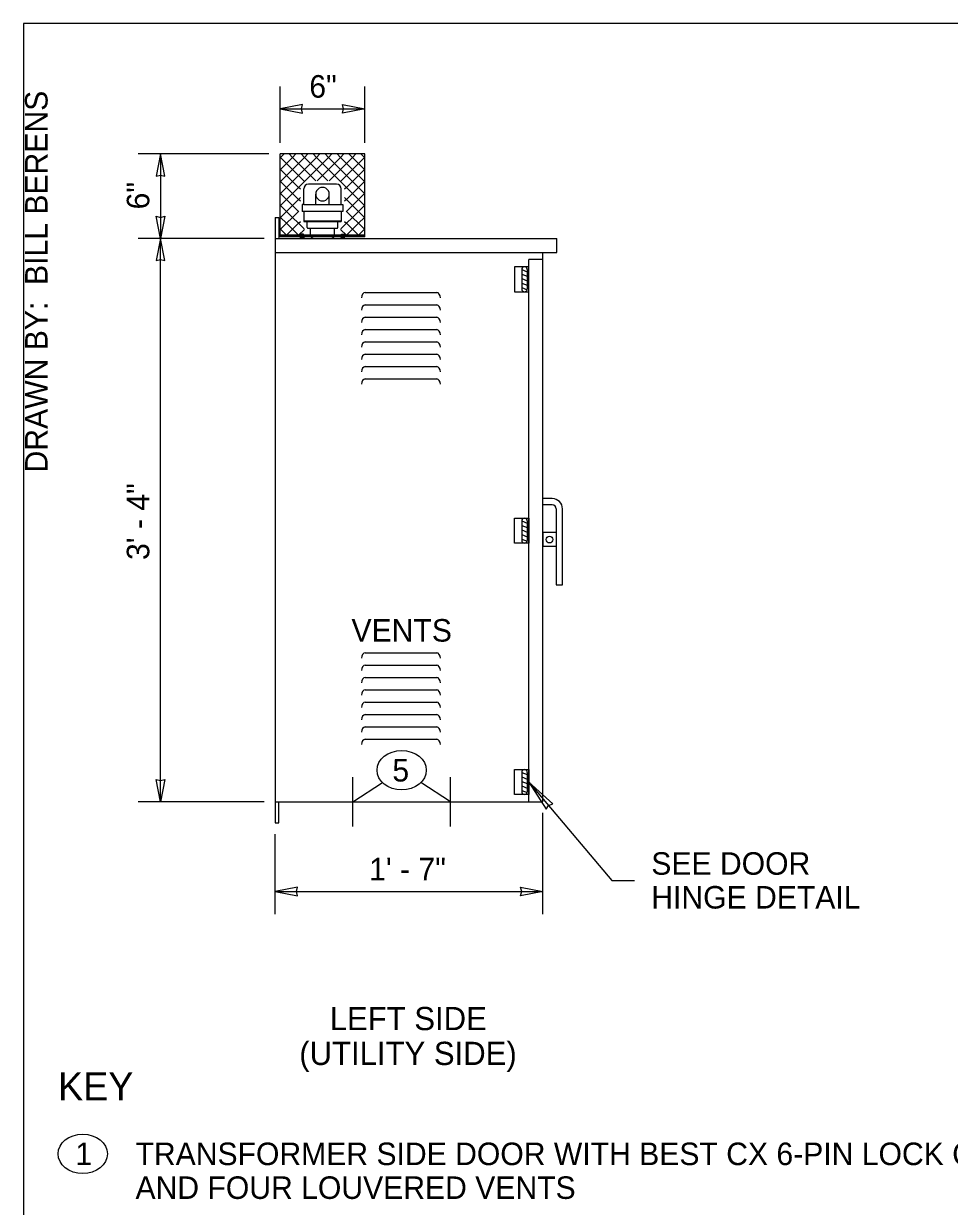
# Model space of a CAD drawing. Extents: x 99862 to 103680, y 99470 to 105076.
# Drawn here: x 99862 to 100520, y 101236 to 102076 of the extents above; entities that cross this region are included whole.
import ezdxf

# ---------------------------------------------------------------- set-up
doc = ezdxf.new("R2010")
doc.units = 0
for name, color, linetype in [('Level 1', 7, 'Continuous'), ('Level 11', 7, 'Continuous'), ('Level 15', 7, 'Continuous'), ('Level 20', 7, 'Continuous'), ('Level 3', 7, 'Continuous'), ('Level 40', 7, 'Continuous'), ('Level 62', 7, 'Continuous')]:
    doc.layers.add(name, color=color, linetype=linetype)

msp = doc.modelspace()

# ---------------------------------------------------------------- linework, layer by layer
at = {"layer": 'Level 1'}
for p, q in [((100044.28, 101925.19), (100044.28, 101982.94)), ((100104.28, 101982.94), (100044.28, 101982.94)), ((100044.28, 101980.71), (100044.5, 101980.49)), ((100044.5, 101980.49), (100044.28, 101980.27)), ((100044.5, 101980.49), (100046.95, 101982.94)), ((100048.75, 101976.24), (100044.5, 101980.49)), ((100044.5, 101971.98), (100048.75, 101976.24)), ((100053, 101980.49), (100048.75, 101976.24)), ((100048.75, 101976.24), (100053, 101971.98)), ((100050.55, 101982.94), (100053, 101980.49)), ((100055.46, 101982.94), (100053, 101980.49)), ((100053, 101980.49), (100057.26, 101976.24)), ((100057.26, 101976.24), (100053, 101971.98)), ((100057.26, 101976.24), (100061.51, 101980.49)), ((100061.51, 101971.98), (100057.26, 101976.24)), ((100061.51, 101980.49), (100059.06, 101982.94)), ((100063.97, 101982.94), (100061.51, 101980.49)), ((100061.51, 101980.49), (100065.77, 101976.24)), ((100065.77, 101976.24), (100061.51, 101971.98)), ((100065.77, 101976.24), (100070.02, 101980.49)), ((100070.02, 101971.98), (100065.77, 101976.24)), ((100070.02, 101980.49), (100067.57, 101982.94)), ((100072.47, 101982.94), (100070.02, 101980.49)), ((100070.02, 101980.49), (100074.28, 101976.24)), ((100074.28, 101976.24), (100070.02, 101971.98)), ((100074.28, 101976.24), (100078.53, 101980.49)), ((100078.53, 101971.98), (100074.28, 101976.24)), ((100078.53, 101980.49), (100076.08, 101982.94)), ((100080.98, 101982.94), (100078.53, 101980.49)), ((100078.53, 101980.49), (100082.78, 101976.24)), ((100082.78, 101976.24), (100078.53, 101971.98)), ((100082.78, 101976.24), (100087.04, 101980.49)), ((100087.04, 101971.98), (100082.78, 101976.24)), ((100087.04, 101980.49), (100084.59, 101982.94)), ((100089.49, 101982.94), (100087.04, 101980.49)), ((100087.04, 101980.49), (100091.29, 101976.24)), ((100091.29, 101976.24), (100087.04, 101971.98)), ((100091.29, 101976.24), (100095.55, 101980.49)), ((100095.55, 101971.98), (100091.29, 101976.24)), ((100093.09, 101982.94), (100095.55, 101980.49)), ((100095.55, 101980.49), (100098, 101982.94)), ((100095.55, 101980.49), (100099.8, 101976.24)), ((100099.8, 101976.24), (100095.55, 101971.98)), ((100099.8, 101976.24), (100104.05, 101980.49)), ((100104.05, 101971.98), (100099.8, 101976.24)), ((100104.05, 101980.49), (100101.6, 101982.94)), ((100104.28, 101980.71), (100104.05, 101980.49)), ((100104.05, 101980.49), (100104.28, 101980.27)), ((100104.28, 101925.19), (100104.28, 101982.95)), ((100044.28, 101972.21), (100044.5, 101971.98)), ((100044.5, 101971.98), (100044.28, 101971.76)), ((100048.75, 101967.73), (100044.5, 101971.98)), ((100053, 101971.98), (100048.75, 101967.73)), ((100053, 101971.98), (100057.26, 101967.73)), ((100057.26, 101967.73), (100061.51, 101971.98)), ((100061.51, 101971.98), (100065.77, 101967.73)), ((100065.77, 101967.73), (100070.02, 101971.98)), ((100070.02, 101971.98), (100074.28, 101967.73)), ((100074.28, 101967.73), (100078.53, 101971.98)), ((100078.53, 101971.98), (100082.78, 101967.73)), ((100082.78, 101967.73), (100087.04, 101971.98)), ((100087.04, 101971.98), (100091.29, 101967.73)), ((100091.29, 101967.73), (100095.55, 101971.98)), ((100095.55, 101971.98), (100099.8, 101967.73)), ((100099.8, 101967.73), (100104.05, 101971.98)), ((100104.28, 101972.2), (100104.05, 101971.98)), ((100104.05, 101971.98), (100104.28, 101971.76)), ((100044.28, 101963.7), (100044.5, 101963.48)), ((100044.5, 101963.48), (100044.28, 101963.25)), ((100044.5, 101963.48), (100048.75, 101967.73)), ((100048.75, 101959.22), (100044.5, 101963.48)), ((100048.75, 101967.73), (100053, 101963.48)), ((100053, 101963.48), (100048.75, 101959.22)), ((100057.26, 101967.73), (100053, 101963.48)), ((100053, 101963.48), (100057.26, 101959.22)), ((100061.51, 101963.48), (100057.26, 101967.73)), ((100057.26, 101959.22), (100061.51, 101963.48)), ((100065.77, 101967.73), (100061.51, 101963.48)), ((100061.51, 101963.48), (100061.73, 101963.26)), ((100084.3, 101961.45), (100064.25, 101961.45)), ((100069.64, 101963.86), (100065.77, 101967.73)), ((100074.28, 101967.73), (100070.4, 101963.86)), ((100078.15, 101963.86), (100074.28, 101967.73)), ((100082.78, 101967.73), (100078.91, 101963.86)), ((100087.04, 101963.48), (100082.78, 101967.73)), ((100086.82, 101963.26), (100087.04, 101963.48)), ((100091.29, 101967.73), (100087.04, 101963.48)), ((100087.04, 101963.48), (100091.29, 101959.22)), ((100095.55, 101963.48), (100091.29, 101967.73)), ((100091.29, 101959.22), (100095.55, 101963.48)), ((100099.8, 101967.73), (100095.55, 101963.48)), ((100095.55, 101963.48), (100099.8, 101959.22)), ((100104.05, 101963.48), (100099.8, 101967.73)), ((100099.8, 101959.22), (100104.05, 101963.48)), ((100104.28, 101963.7), (100104.05, 101963.48)), ((100104.05, 101963.48), (100104.28, 101963.26)), ((100044.28, 101955.19), (100044.5, 101954.97)), ((100044.5, 101954.97), (100044.28, 101954.75)), ((100044.5, 101954.97), (100048.75, 101959.22)), ((100048.75, 101950.71), (100044.5, 101954.97)), ((100048.75, 101959.22), (100053, 101954.97)), ((100053, 101954.97), (100048.75, 101950.71)), ((100057.26, 101959.22), (100053, 101954.97)), ((100053, 101954.97), (100057.26, 101950.71)), ((100058.63, 101957.85), (100057.26, 101959.22)), ((100057.26, 101950.71), (100058.63, 101952.09)), ((100061.04, 101947.01), (100061.04, 101958.24)), ((100069.46, 101947.01), (100069.46, 101954.39)), ((100079.09, 101947.01), (100079.09, 101954.39)), ((100087.51, 101947.01), (100087.51, 101958.24)), ((100091.29, 101959.22), (100089.92, 101957.85)), ((100089.92, 101952.09), (100091.29, 101950.71)), ((100095.55, 101954.97), (100091.29, 101959.22)), ((100091.29, 101950.71), (100095.55, 101954.97)), ((100099.8, 101959.22), (100095.55, 101954.97)), ((100095.55, 101954.97), (100099.8, 101950.71)), ((100104.05, 101954.97), (100099.8, 101959.22)), ((100099.8, 101950.71), (100104.05, 101954.97)), ((100104.28, 101955.19), (100104.05, 101954.97)), ((100104.05, 101954.97), (100104.28, 101954.75)), ((100044.28, 101946.68), (100044.5, 101946.46)), ((100044.5, 101946.46), (100044.28, 101946.24)), ((100044.5, 101946.46), (100048.75, 101950.71)), ((100048.75, 101942.2), (100044.5, 101946.46)), ((100048.75, 101950.71), (100053, 101946.46)), ((100053, 101946.46), (100048.75, 101942.2)), ((100057.26, 101950.71), (100053, 101946.46)), ((100053, 101946.46), (100057.26, 101942.2)), ((100058.56, 101949.42), (100057.26, 101950.71)), ((100061.04, 101947.01), (100059.84, 101947.01)), ((100059.84, 101947.01), (100059.84, 101942.2)), ((100061.04, 101947.01), (100087.51, 101947.01)), ((100087.51, 101947.01), (100088.71, 101947.01)), ((100088.71, 101947.01), (100088.71, 101942.2)), ((100091.29, 101950.71), (100090, 101949.42)), ((100095.55, 101946.46), (100091.29, 101950.71)), ((100091.29, 101942.2), (100095.55, 101946.46)), ((100099.8, 101950.71), (100095.55, 101946.46)), ((100095.55, 101946.46), (100099.8, 101942.2)), ((100104.05, 101946.46), (100099.8, 101950.71)), ((100099.8, 101942.2), (100104.05, 101946.46)), ((100104.28, 101946.68), (100104.05, 101946.46)), ((100104.05, 101946.46), (100104.28, 101946.24)), ((100044.28, 101938.17), (100044.5, 101937.95)), ((100044.5, 101937.95), (100044.28, 101937.73)), ((100044.5, 101937.95), (100048.75, 101942.2)), ((100048.75, 101933.7), (100044.5, 101937.95)), ((100048.75, 101942.2), (100053, 101937.95)), ((100053, 101937.95), (100048.75, 101933.7)), ((100057.26, 101942.2), (100053, 101937.95)), ((100053, 101937.95), (100057.26, 101933.7)), ((100057.26, 101942.2), (100057.43, 101942.38)), ((100057.43, 101942.03), (100057.26, 101942.2)), ((100057.26, 101933.7), (100058.63, 101935.07)), ((100088.71, 101942.2), (100059.84, 101942.2)), ((100061.04, 101942.2), (100061.04, 101934.98)), ((100061.04, 101935.58), (100087.51, 101935.58)), ((100061.04, 101934.98), (100087.51, 101934.98)), ((100063.45, 101930.77), (100063.45, 101934.98)), ((100085.1, 101930.77), (100085.1, 101934.98)), ((100087.51, 101942.2), (100087.51, 101934.98)), ((100089.92, 101935.07), (100091.29, 101933.7)), ((100091.12, 101942.38), (100091.29, 101942.2)), ((100091.29, 101942.2), (100091.12, 101942.03)), ((100095.55, 101937.95), (100091.29, 101942.2)), ((100091.29, 101933.7), (100095.55, 101937.95)), ((100099.8, 101942.2), (100095.55, 101937.95)), ((100095.55, 101937.95), (100099.8, 101933.7)), ((100104.05, 101937.95), (100099.8, 101942.2)), ((100099.8, 101933.7), (100104.05, 101937.95)), ((100104.28, 101938.17), (100104.05, 101937.95)), ((100104.05, 101937.95), (100104.28, 101937.73)), ((100044.28, 101929.66), (100044.5, 101929.44)), ((100044.5, 101929.44), (100044.28, 101929.22)), ((100044.5, 101929.44), (100048.75, 101933.7)), ((100048.75, 101925.19), (100044.5, 101929.44)), ((100048.75, 101933.7), (100053, 101929.44)), ((100053, 101929.44), (100048.75, 101925.19)), ((100057.26, 101933.7), (100053, 101929.44)), ((100053, 101929.44), (100057.26, 101925.19)), ((100061.22, 101929.73), (100057.26, 101933.7)), ((100057.26, 101925.19), (100061.4, 101929.33)), ((100064.05, 101930.16), (100084.5, 101930.16)), ((100065.85, 101925.35), (100065.85, 101930.16)), ((100082.7, 101925.35), (100082.7, 101930.16)), ((100087.15, 101929.33), (100091.29, 101925.19)), ((100091.29, 101933.7), (100087.33, 101929.73)), ((100095.55, 101929.44), (100091.29, 101933.7)), ((100091.29, 101925.19), (100095.55, 101929.44)), ((100099.8, 101933.7), (100095.55, 101929.44)), ((100095.55, 101929.44), (100099.8, 101925.19)), ((100104.05, 101929.44), (100099.8, 101933.7)), ((100099.8, 101925.19), (100104.05, 101929.44)), ((100104.28, 101929.66), (100104.05, 101929.44)), ((100104.05, 101929.44), (100104.28, 101929.22)), ((100104.28, 101925.19), (100044.28, 101925.19)), ((100044.28, 101924.15), (100044.28, 101925.09)), ((100104.28, 101925.09), (100044.28, 101925.09)), ((100104.28, 101924.15), (100044.28, 101924.15)), ((100068.26, 101922.94), (100080.29, 101922.94)), ((100104.28, 101924.15), (100104.28, 101925.09)), ((100215.78, 101900.87), (100215.78, 101887.1)), ((100215.78, 101900.87), (100219.78, 101899.33)), ((100219.78, 101900.87), (100219.78, 101887.1)), ((100220.78, 101885.1), (100220.78, 101902.87)), ((100215.78, 101897.66), (100219.78, 101896.11)), ((100215.78, 101894.44), (100219.78, 101892.9)), ((100215.78, 101891.23), (100219.78, 101889.68)), ((100215.78, 101888.01), (100219.68, 101886.5)), ((100237.51, 101738.17), (100230.78, 101738.17)), ((100237.51, 101733.73), (100230.78, 101733.73)), ((100220.78, 101724.33), (100220.78, 101706.56)), ((100240.33, 101730.92), (100240.33, 101676.86)), ((100244.76, 101676.86), (100244.76, 101730.92)), ((100215.78, 101722.33), (100215.78, 101708.56)), ((100215.78, 101722.33), (100219.78, 101720.79)), ((100215.78, 101719.11), (100219.78, 101717.57)), ((100215.78, 101715.9), (100219.78, 101714.36)), ((100219.78, 101722.33), (100219.78, 101708.56)), ((100215.78, 101712.68), (100219.78, 101711.14)), ((100215.78, 101709.47), (100219.68, 101707.96)), ((100240.33, 101714.07), (100230.78, 101714.07)), ((100230.78, 101714.07), (100230.78, 101704.07)), ((100240.33, 101704.07), (100230.78, 101704.07)), ((100240.33, 101676.86), (100244.76, 101676.86)), ((100215.78, 101543.79), (100215.78, 101530.02)), ((100215.78, 101543.79), (100219.78, 101542.24)), ((100215.78, 101540.57), (100219.78, 101539.03)), ((100219.78, 101543.79), (100219.78, 101530.02)), ((100220.78, 101545.79), (100220.78, 101528.02)), ((100215.78, 101537.36), (100219.78, 101535.81)), ((100215.78, 101534.14), (100219.78, 101532.6)), ((100215.78, 101530.93), (100219.68, 101529.42))]:
    msp.add_line(p, q, dxfattribs=at)
msp.add_lwpolyline([(99862, 99999.5), (103151, 99999.5), (103151, 102075.5), (99862, 102075.5)], close=True, dxfattribs=at)
for points in [[(100220.78, 101902.87), (100210.78, 101902.87), (100210.78, 101885.1), (100220.78, 101885.1)], [(100220.78, 101706.56), (100210.78, 101706.56), (100210.78, 101724.33), (100220.78, 101724.33)], [(100220.78, 101528.02), (100210.78, 101528.02), (100210.78, 101545.79), (100220.78, 101545.79)]]:
    msp.add_lwpolyline(points, dxfattribs=at)
msp.add_circle((100235.55, 101709.07), 2.37, dxfattribs=at)
for centre, radius, start, end in [((100064.25, 101958.24), 3.21, 90, 180), ((100084.3, 101958.24), 3.21, 0, 90), ((100074.28, 101954.39), 4.81, 359.99971, 180), ((100074.28, 101954.39), 4.81, 180, 0.00029), ((100064.05, 101930.77), 0.602, 180, 270), ((100084.5, 101930.77), 0.602, 270, 0), ((100068.26, 101925.35), 2.41, 180, 270), ((100080.29, 101925.35), 2.41, 270, 0), ((100217.78, 101900.87), 2, 90, 180), ((100217.78, 101900.87), 2, 0, 90), ((100217.78, 101887.1), 2, 180, 270), ((100217.78, 101887.1), 2, 270, 0), ((100237.51, 101730.92), 7.25, 0, 90), ((100237.51, 101730.92), 2.82, 0, 90), ((100217.78, 101722.33), 2, 90, 180), ((100217.78, 101722.33), 2, 0, 90), ((100217.78, 101708.56), 2, 180, 270), ((100217.78, 101708.56), 2, 270, 0), ((100217.78, 101543.79), 2, 90, 180), ((100217.78, 101543.79), 2, 0, 90), ((100217.78, 101530.02), 2, 180, 270), ((100217.78, 101530.02), 2, 270, 0)]:
    msp.add_arc(centre, radius, start, end, dxfattribs=at)
at = {"layer": 'Level 11'}
for p, q in [((100104.54, 101884.5), (100155.44, 101884.5)), ((100104.54, 101875.73), (100155.44, 101875.73)), ((100104.54, 101866.97), (100155.44, 101866.97)), ((100104.54, 101858.21), (100155.44, 101858.21)), ((100104.54, 101849.44), (100155.44, 101849.44)), ((100104.54, 101840.68), (100155.44, 101840.68)), ((100104.54, 101831.92), (100155.44, 101831.92)), ((100104.54, 101823.15), (100155.44, 101823.15)), ((100104.54, 101628.62), (100155.44, 101628.62)), ((100104.54, 101619.85), (100155.44, 101619.85)), ((100104.54, 101611.09), (100155.44, 101611.09)), ((100104.54, 101602.33), (100155.44, 101602.33)), ((100104.54, 101593.56), (100155.44, 101593.56)), ((100104.54, 101584.8), (100155.44, 101584.8)), ((100104.54, 101576.04), (100155.44, 101576.04)), ((100104.54, 101567.27), (100155.44, 101567.27))]:
    msp.add_line(p, q, dxfattribs=at)
for centre, start_param, end_param in [((100104.54, 101880.86), 0, 1.570796), ((100155.44, 101880.86), 4.712389, 6.283185), ((100104.54, 101872.1), 0, 1.570796), ((100155.44, 101872.1), 4.712389, 6.283185), ((100104.54, 101863.33), 0, 1.570796), ((100155.44, 101863.33), 4.712389, 6.283185), ((100104.54, 101854.57), 0, 1.570796), ((100155.44, 101854.57), 4.712389, 6.283185), ((100104.54, 101845.81), 0, 1.570796), ((100155.44, 101845.81), 4.712389, 6.283185), ((100104.54, 101837.04), 0, 1.570796), ((100155.44, 101837.04), 4.712389, 6.283185), ((100104.54, 101828.28), 0, 1.570796), ((100155.44, 101828.28), 4.712389, 6.283185), ((100104.54, 101819.51), 0, 1.570796), ((100155.44, 101819.51), 4.712389, 6.283185), ((100104.54, 101624.98), 0, 1.570796), ((100155.44, 101624.98), 4.712389, 6.283185), ((100104.54, 101616.22), 0, 1.570796), ((100155.44, 101616.22), 4.712389, 6.283185), ((100104.54, 101607.45), 0, 1.570796), ((100155.44, 101607.45), 4.712389, 6.283185), ((100104.54, 101598.69), 0, 1.570796), ((100155.44, 101598.69), 4.712389, 6.283185), ((100104.54, 101589.93), 0, 1.570796), ((100155.44, 101589.93), 4.712389, 6.283185), ((100104.54, 101581.16), 0, 1.570796), ((100155.44, 101581.16), 4.712389, 6.283185), ((100104.54, 101572.4), 0, 1.570796), ((100155.44, 101572.4), 4.712389, 6.283185), ((100104.54, 101563.63), 0, 1.570796), ((100155.44, 101563.63), 4.712389, 6.283185)]:
    msp.add_ellipse(centre, major_axis=(0, 3.64), ratio=0.707107, start_param=start_param, end_param=end_param, dxfattribs=at)
at = {"layer": 'Level 15'}
for p, q in [((100044.28, 101990.95), (100044.28, 102030.95)), ((100104.28, 101990.95), (100104.28, 102030.95)), ((100044.28, 102014.95), (100104.28, 102014.95)), ((100036.28, 101982.94), (99943.25, 101982.94)), ((99959.25, 101982.94), (99959.25, 101922.94)), ((100032.78, 101922.94), (99943.25, 101922.94)), ((99959.25, 101522.94), (99959.25, 101922.94)), ((100040.78, 101912.94), (100230.78, 101912.94)), ((100220.78, 101522.94), (100220.78, 101907.94)), ((100230.78, 101907.94), (100220.78, 101907.94)), ((100095.78, 101505.44), (100095.78, 101540.44)), ((100165.23, 101505.44), (100165.23, 101540.44)), ((100095.78, 101522.94), (100116.86, 101536.5)), ((100165.23, 101522.94), (100144.14, 101536.5)), ((100220.78, 101536.9), (100279.83, 101467.06)), ((100032.78, 101522.94), (99943.25, 101522.94)), ((100043.28, 101507.94), (100043.28, 101522.94)), ((100230.78, 101443.08), (100230.78, 101514.94)), ((100040.78, 101507.94), (100043.28, 101507.94)), ((100040.78, 101443.08), (100040.78, 101499.94)), ((100279.83, 101467.06), (100295.83, 101467.06)), ((100040.78, 101459.08), (100230.78, 101459.08))]:
    msp.add_line(p, q, dxfattribs=at)
for points in [[(100044.28, 102014.95), (100060, 102011.86), (100059.27, 102014.95), (100060, 102018.03)], [(100104.28, 102014.95), (100088.55, 102011.86), (100089.28, 102014.95), (100088.55, 102018.03)], [(99959.25, 101982.94), (99956.16, 101967.22), (99959.25, 101967.95), (99962.33, 101967.22)], [(99959.25, 101922.94), (99956.16, 101938.67), (99959.25, 101937.94), (99962.33, 101938.67)], [(99959.25, 101922.94), (99956.16, 101907.22), (99959.25, 101907.95), (99962.33, 101907.22)], [(99959.25, 101522.94), (99956.16, 101538.67), (99959.25, 101537.94), (99962.33, 101538.67)], [(100220.78, 101536.9), (100233.24, 101517.54), (100234.83, 101520.28), (100237.79, 101521.4)], [(100040.78, 101459.08), (100056.5, 101456), (100055.77, 101459.08), (100056.5, 101462.17)], [(100230.78, 101459.08), (100215.05, 101456), (100215.78, 101459.08), (100215.05, 101462.17)]]:
    msp.add_lwpolyline(points, close=True, dxfattribs=at)
at = {"layer": 'Level 20'}
for centre in [(100130.5, 101545.27), (99903.95, 101272.85)]:
    msp.add_ellipse(centre, major_axis=(-17.5, 0), ratio=0.8, dxfattribs=at)
at = {"layer": 'Level 40'}
for p, q in [((100040.78, 101937.94), (100040.78, 101507.94)), ((100040.78, 101937.94), (100043.28, 101937.94)), ((100043.28, 101937.94), (100043.28, 101922.94)), ((100040.78, 101922.94), (100240.78, 101922.94)), ((100240.78, 101912.94), (100240.78, 101922.94)), ((100230.78, 101522.94), (100230.78, 101912.94)), ((100230.78, 101912.94), (100240.78, 101912.94)), ((100040.78, 101522.94), (100230.78, 101522.94))]:
    msp.add_line(p, q, dxfattribs=at)
for points in [[(100060.82, 101925.11), (100060.82, 101925.88), (100058.85, 101925.88), (100058.85, 101925.11)], [(100087.73, 101925.11), (100087.73, 101925.88), (100089.7, 101925.88), (100089.7, 101925.11)], [(100061.18, 101923.19), (100061.18, 101922.94), (100058.49, 101922.94), (100058.49, 101923.19)], [(100061.15, 101923.35), (100061.15, 101923.19), (100058.52, 101923.19), (100058.52, 101923.35)], [(100060.82, 101923.35), (100060.82, 101924.15), (100058.85, 101924.15), (100058.85, 101923.35)], [(100087.37, 101923.19), (100087.37, 101922.94), (100090.06, 101922.94), (100090.06, 101923.19)], [(100087.4, 101923.35), (100087.4, 101923.19), (100090.03, 101923.19), (100090.03, 101923.35)], [(100087.73, 101923.35), (100087.73, 101924.15), (100089.7, 101924.15), (100089.7, 101923.35)]]:
    msp.add_lwpolyline(points, close=True, dxfattribs=at)

# ---------------------------------------------------------------- texts
at = {"layer": 'Level 20'}
for s, rotation, p in [('6"', 360, (100064.91, 102022.95)), ('6"', 90, (99951.25, 101943.58)), ('3\' - 4"', 90, (99951.25, 101694.61)), ('VENTS', 360, (100094.88, 101636.62)), ('1\' - 7"', 360, (100107.44, 101467.08)), ('TRANSFORMER SIDE DOOR WITH BEST CX 6-PIN LOCK CORE', 360, (99941.45, 101264.85)), ('AND FOUR LOUVERED VENTS', 360, (99941.45, 101240.85))]:
    msp.add_text(s, height=16, rotation=rotation, dxfattribs=at).set_placement(p)
for s, height, p in [('5', 16, (100123.92, 101537.27)), ('SEE DOOR', 16, (100307.83, 101471.06)), ('HINGE DETAIL', 16, (100307.83, 101447.06)), ('LEFT SIDE', 16.5, (100079.43, 101360.69)), ('(UTILITY SIDE)', 16.5, (100057.8, 101335.94)), ('1', 16, (99898.67, 101264.85))]:
    msp.add_text(s, height=height, dxfattribs=at).set_placement(p)
at = {"layer": 'Level 3'}
msp.add_text('KEY', height=20, rotation=360, dxfattribs=at).set_placement((99886.45, 101310.85))
at = {"layer": 'Level 62'}
msp.add_text('DRAWN BY:  BILL BERENS', height=16, rotation=90, dxfattribs=at).set_placement((99879, 101756.77))

doc.saveas('drawing.dxf')
